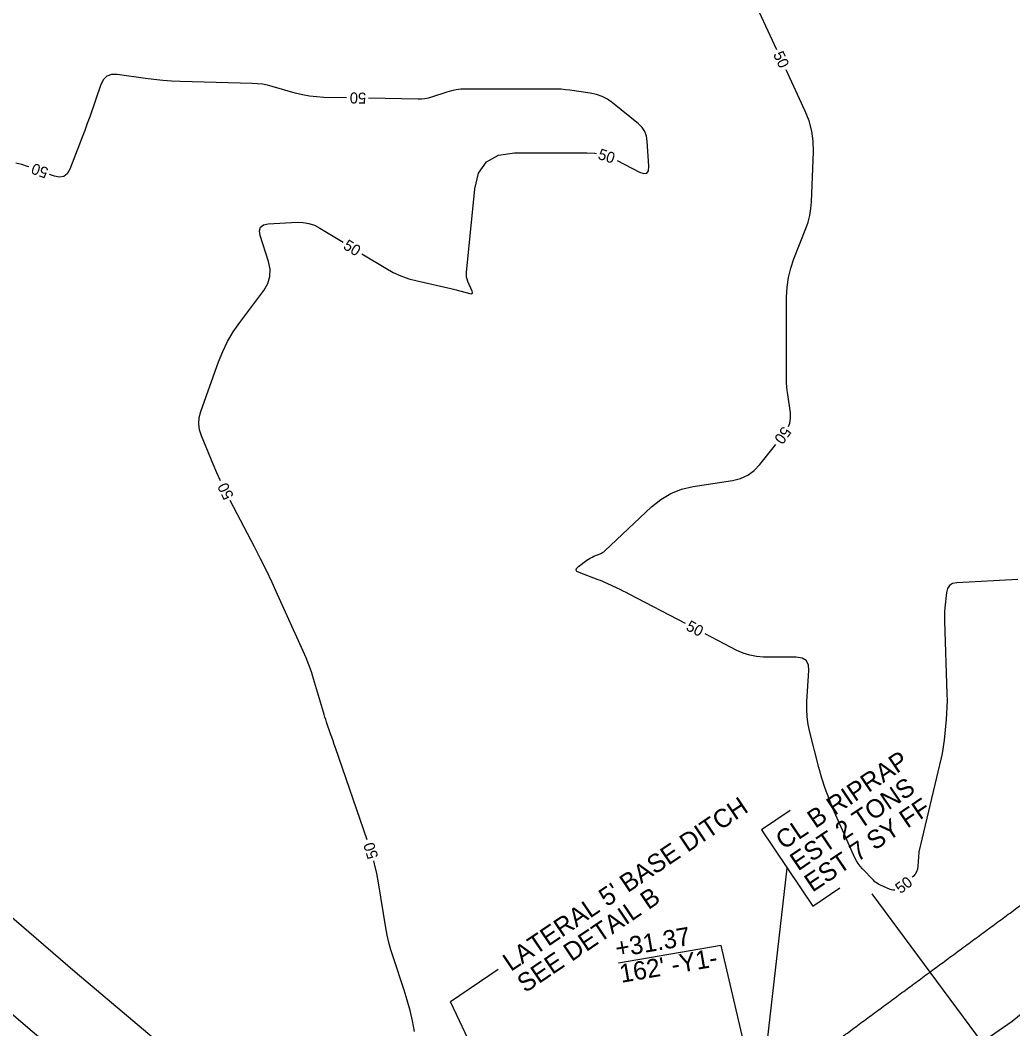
# Model space of a CAD drawing. Extents: x 2384780 to 2405861, y 547869 to 573706.
# Drawn here: x 2392121.2 to 2392391.8, y 553555 to 553830.1 of the extents above; entities that cross this region are included whole.
import ezdxf

# ---------------------------------------------------------------- set-up
doc = ezdxf.new("R2010")
doc.units = 0
for name, color, linetype in [('Breaklines', 7, 'Continuous'), ('Old_Level_5', 7, 'Continuous'), ('Old_Level_61', 7, 'Continuous'), ('Old_Level_63', 7, 'Continuous'), ('Prop Buffer Zone 1', 7, 'Continuous'), ('Prop Buffer Zone 2', 7, 'Continuous'), ('Sheet Plan CELL', 7, 'Continuous')]:
    doc.layers.add(name, color=color, linetype=linetype)

msp = doc.modelspace()

# ---------------------------------------------------------------- linework, layer by layer
at = {"layer": 'Breaklines'}
msp.add_line((2392317.6025, 553488.70725), (2392330.29475, 553598.83), dxfattribs=at)
msp.add_lwpolyline([(2392331.1045, 553614.50125), (2392323.28275, 553609.2255), (2392337.30675, 553588.43425), (2392344.6395, 553593.38025)], dxfattribs=at)
at = {"layer": 'Old_Level_5'}
for p in [(2392251.46575, 553571.12025), (2392281.58, 553471.52125)]:
    msp.add_line(p, (2392238.4535, 553562.3435), dxfattribs=at)
at = {"layer": 'Old_Level_61'}
for points in [[(2392327.47975, 553821.98375), (2392320.29075, 553837.53075), (2392320.1375, 553837.8405), (2392319.96825, 553838.1405), (2392319.783, 553838.43075), (2392319.582, 553838.71175), (2392318.899, 553839.6135), (2392318.74225, 553839.79225), (2392318.5645, 553839.94175), (2392318.36575, 553840.062), (2392318.14625, 553840.15325), (2392286.3615, 553850.74), (2392283.187, 553851.817), (2392280.0255, 553852.92975), (2392276.8765, 553854.07775), (2392273.74, 553855.261), (2392263.51575, 553859.18475), (2392261.307, 553859.8885), (2392259.06275, 553860.31825), (2392256.78325, 553860.47425), (2392254.468, 553860.35625), (2392244.3405, 553859.249), (2392242.21325, 553859.19075), (2392242.176, 553859.19625)], [(2392210.1315, 553808.92625), (2392203.986, 553809.051), (2392202.0025, 553809.155), (2392200.038, 553809.3855), (2392198.09275, 553809.7425), (2392196.16625, 553810.22625), (2392189.9045, 553812.01325), (2392188.55625, 553812.353), (2392187.1945, 553812.60675), (2392185.8195, 553812.7745), (2392184.43125, 553812.85625), (2392164.76075, 553813.40025), (2392162.383, 553813.499), (2392160.011, 553813.66325), (2392157.64425, 553813.8935), (2392155.283, 553814.18925), (2392147.57875, 553815.263), (2392146.06575, 553815.2675), (2392144.82825, 553814.821), (2392143.8665, 553813.9235), (2392143.18025, 553812.575), (2392140.114, 553803.7725), (2392139.448, 553801.8895), (2392138.76425, 553800.01325), (2392138.06275, 553798.1435), (2392137.34325, 553796.28025), (2392134.65925, 553789.42775), (2392133.9705, 553788.20975), (2392133.05475, 553787.4925), (2392131.91175, 553787.27575), (2392130.5415, 553787.55975), (2392129.18825, 553788.047)], [(2392330.66175, 553719.2265), (2392331.01925, 553720.15575), (2392331.236, 553721.55525), (2392331.16025, 553723.0325), (2392330.43625, 553727.9855), (2392330.3005, 553729.04825), (2392330.2035, 553730.114), (2392330.14575, 553731.18225), (2392330.12675, 553732.2535), (2392330.13675, 553754.568), (2392330.262, 553757.252), (2392330.636, 553759.88875), (2392331.25825, 553762.478), (2392332.129, 553765.02), (2392335.37925, 553773.24675), (2392335.99775, 553775.02575), (2392336.45975, 553776.838), (2392336.76525, 553778.68275), (2392336.91475, 553780.5605), (2392337.42625, 553794.16825), (2392337.369, 553797.05075), (2392336.97825, 553799.86625), (2392336.254, 553802.615), (2392335.196, 553805.297), (2392329.998, 553816.538)], [(2392283.95225, 553791.851), (2392290.0665, 553788.656), (2392291.226, 553788.2325), (2392292.0285, 553788.3605), (2392292.474, 553789.04025), (2392292.56275, 553790.2715), (2392292.15625, 553797.0815), (2392291.938, 553798.47325), (2392291.4575, 553799.73025), (2392290.7145, 553800.85225), (2392289.7095, 553801.8395), (2392282.66625, 553807.541), (2392281.2875, 553808.5155), (2392279.81775, 553809.281), (2392278.2565, 553809.83775), (2392276.60425, 553810.18525), (2392271.05775, 553810.979), (2392269.86775, 553811.12775), (2392268.67475, 553811.234), (2392267.47875, 553811.298), (2392266.2795, 553811.31925), (2392242.685, 553811.31925), (2392241.351, 553811.26625), (2392240.0345, 553811.107), (2392238.73475, 553810.842), (2392237.4525, 553810.471), (2392233.2915, 553809.0855), (2392232.394, 553808.828), (2392231.4845, 553808.6495), (2392230.56275, 553808.55025), (2392229.62925, 553808.52975), (2392216.13025, 553808.80425)], [(2392214.35575, 553766.38275), (2392220.82175, 553762.4345), (2392222.85075, 553761.30525), (2392224.951, 553760.3525), (2392227.12275, 553759.576), (2392229.36575, 553758.97575), (2392238.54475, 553756.91275), (2392239.271, 553756.744), (2392239.99475, 553756.565), (2392240.71575, 553756.3755), (2392241.43425, 553756.17575), (2392243.77675, 553755.50625), (2392244.19025, 553755.44075), (2392244.42725, 553755.531), (2392244.48725, 553755.77725), (2392244.3705, 553756.1795), (2392243.22825, 553758.85375), (2392243.02175, 553759.43275), (2392242.89175, 553760.0235), (2392242.838, 553760.626), (2392242.861, 553761.24025), (2392245.11675, 553784.11375), (2392246.15525, 553788.4025), (2392248.3045, 553791.46575), (2392251.564, 553793.30375), (2392255.934, 553793.9165), (2392275.68675, 553793.9165), (2392277.81275, 553793.79175), (2392278.27775, 553793.70725)], [(2392123.54325, 553790.08025), (2392123.1625, 553790.21725), (2392121.56875, 553790.71975), (2392119.9505, 553791.08825)], [(2392175.77725, 553704.41), (2392174.75675, 553706.659), (2392173.75375, 553709.00375), (2392170.56025, 553716.701), (2392170.03675, 553718.3545), (2392169.835, 553720.01575), (2392169.955, 553721.685), (2392170.39675, 553723.362), (2392175.24425, 553736.88325), (2392176.3835, 553739.72675), (2392177.7235, 553742.4625), (2392179.26425, 553745.09025), (2392181.00575, 553747.61025), (2392187.553, 553756.37575), (2392188.65075, 553758.2305), (2392189.237, 553760.1705), (2392189.312, 553762.19575), (2392188.8755, 553764.3065), (2392186.61425, 553771.34025), (2392186.388, 553772.67), (2392186.67775, 553773.645), (2392187.48425, 553774.26475), (2392188.80675, 553774.52975), (2392196.642, 553774.96325), (2392198.2905, 553774.935), (2392199.878, 553774.66425), (2392201.40475, 553774.1515), (2392202.87025, 553773.39625), (2392209.235, 553769.50975)], [(2392302.6005, 553665.50475), (2392287.2475, 553673.53575), (2392286.424, 553673.9605), (2392285.59525, 553674.375), (2392284.762, 553674.78), (2392283.9235, 553675.17475), (2392281.177, 553676.4485), (2392280.58625, 553676.716), (2392279.9905, 553676.97175), (2392279.39, 553677.21625), (2392278.78475, 553677.4495), (2392273.582, 553679.397), (2392272.96325, 553679.72525), (2392272.7175, 553680.1075), (2392272.8455, 553680.54325), (2392273.34675, 553681.03275), (2392275.6675, 553682.775), (2392276.12125, 553683.093), (2392276.593, 553683.37925), (2392277.0825, 553683.6335), (2392277.59, 553683.85575), (2392279.277, 553684.53025), (2392279.62875, 553684.69), (2392279.96075, 553684.8805), (2392280.2735, 553685.10175), (2392280.5665, 553685.3535), (2392293.272, 553697.3355), (2392295.7975, 553699.3925), (2392298.5395, 553701.005), (2392301.4985, 553702.17325), (2392304.67425, 553702.897), (2392315.40225, 553704.535), (2392317.5935, 553705.07075), (2392319.569, 553705.97575), (2392321.32925, 553707.25025), (2392322.87425, 553708.89375), (2392327.17575, 553714.36675)], [(2392215.7645, 553606.50225), (2392207.149, 553631.575), (2392206.815, 553632.547), (2392206.48075, 553633.51925), (2392206.14675, 553634.49125), (2392205.81275, 553635.4635), (2392204.7215, 553638.639), (2392204.49125, 553639.32075), (2392204.26825, 553640.0045), (2392204.0525, 553640.69075), (2392203.84375, 553641.3795), (2392201.153, 553650.42925), (2392200.54425, 553652.3565), (2392199.87125, 553654.25975), (2392199.13375, 553656.13875), (2392198.33175, 553657.994), (2392191.36025, 553673.39825), (2392189.84375, 553676.688), (2392188.282, 553679.956), (2392186.675, 553683.20175), (2392185.02275, 553686.42575), (2392178.44775, 553699.0375)], [(2392393.2035, 553677.523), (2392376.52575, 553676.649), (2392375.38875, 553676.43075), (2392374.54025, 553675.90975), (2392373.98075, 553675.0865), (2392373.71025, 553673.9605), (2392373.2975, 553669.78875), (2392373.224, 553668.89425), (2392373.18, 553667.99875), (2392373.16575, 553667.1025), (2392373.181, 553666.205), (2392373.8495, 553646.2945), (2392373.87925, 553644.55675), (2392373.8515, 553642.82075), (2392373.7665, 553641.0865), (2392373.624, 553639.3545), (2392373.06475, 553633.69875), (2392372.92475, 553632.49025), (2392372.74475, 553631.2885), (2392372.52475, 553630.09325), (2392372.2645, 553628.90475), (2392366.19525, 553603.2335), (2392366.19425, 553603.229), (2392366.1935, 553603.22425), (2392366.193, 553603.2195), (2392366.1925, 553603.2145), (2392366.1915, 553603.199), (2392366.1915, 553603.1955), (2392366.19125, 553603.19225), (2392366.191, 553603.18875), (2392366.19075, 553603.1855), (2392365.957, 553599.2965), (2392365.836, 553598.4975), (2392365.5725, 553597.7665), (2392365.167, 553597.10375), (2392364.61925, 553596.50925), (2392364.396, 553596.307)], [(2392359.6825, 553592.7505), (2392359.135, 553592.751), (2392358.35675, 553592.98625), (2392355.75375, 553594.1375), (2392355.21275, 553594.40825), (2392354.7055, 553594.72725), (2392354.23175, 553595.09425), (2392353.792, 553595.50975), (2392350.801, 553598.617), (2392350.193, 553599.30525), (2392349.6515, 553600.038), (2392349.17625, 553600.8155), (2392348.76725, 553601.6375), (2392342.87625, 553614.87125), (2392341.70425, 553617.662), (2392340.654, 553620.49475), (2392339.72525, 553623.37), (2392338.9185, 553626.28725), (2392336.48175, 553635.88625), (2392336.0405, 553637.95075), (2392335.7615, 553640.03075), (2392335.6445, 553642.126), (2392335.6895, 553644.23675), (2392336.19275, 553652.69725), (2392336.06, 553654.28475), (2392335.44625, 553655.42125), (2392334.35175, 553656.1065), (2392332.776, 553656.341), (2392323.83275, 553656.38475), (2392321.94375, 553656.504), (2392320.10925, 553656.84275), (2392318.32925, 553657.4015), (2392316.60375, 553658.18), (2392307.91725, 553662.72375)], [(2392228.71825, 553554.2515), (2392228.15225, 553557.11275), (2392227.484, 553559.948), (2392226.71375, 553562.75725), (2392225.84125, 553565.54025), (2392222.825, 553574.5895), (2392222.218, 553576.5385), (2392221.68975, 553578.50675), (2392221.2405, 553580.49475), (2392220.87025, 553582.502), (2392218.86025, 553594.7505), (2392218.37525, 553597.36175), (2392217.782, 553599.94525), (2392217.55375, 553600.77725)]]:
    msp.add_lwpolyline(points, dxfattribs=at)
at = {"layer": 'Old_Level_63'}
msp.add_line((2392465.5955, 553440.27425), (2392353.48525, 553591.8015), dxfattribs=at)
msp.add_lwpolyline([(2392322.107, 553535.63125), (2392312.25, 553577.70575), (2392284.3215, 553572.89)], dxfattribs=at)
msp.add_spline([(2392322.107, 553535.63125), (2392325.8135, 553538.37375), (2392329.521, 553541.1165), (2392333.2305, 553543.86075), (2392336.94225, 553546.60625), (2392340.65775, 553549.3545), (2392344.3735, 553552.102), (2392348.0935, 553554.8525), (2392351.814, 553557.6025), (2392355.53775, 553560.35425), (2392359.26675, 553563.109), (2392362.9945, 553565.86175), (2392366.727, 553568.61725), (2392370.46275, 553571.3735), (2392374.19675, 553574.1275), (2392377.936, 553576.8845), (2392381.68125, 553579.644), (2392385.42425, 553582.4005), (2392389.17375, 553585.1605), (2392392.926, 553587.92025), (2392396.6795, 553590.6795), (2392400.43925, 553593.44125), (2392404.19925, 553596.2015), (2392407.96325, 553598.96225), (2392411.72825, 553601.7215), (2392415.49925, 553604.48325), (2392419.27425, 553607.24525), (2392423.0475, 553610.00375), (2392426.82675, 553612.76425), (2392430.6105, 553615.525), (2392434.39825, 553618.286), (2392438.18925, 553621.04675), (2392441.984, 553623.807), (2392445.781, 553626.566), (2392449.57925, 553629.32275), (2392453.38325, 553632.08075), (2392457.19475, 553634.84075), (2392461.00575, 553637.5965), (2392464.82025, 553640.352), (2392468.64175, 553643.10825), (2392472.46475, 553645.8625), (2392476.2925, 553648.61625), (2392480.12425, 553651.36875), (2392483.961, 553654.12075), (2392487.79725, 553656.8685), (2392491.6425, 553659.619), (2392495.49, 553662.366), (2392499.34225, 553665.11275), (2392503.199, 553667.85775), (2392507.05775, 553670.6), (2392510.9275, 553673.34525), (2392514.7955, 553676.08425), (2392518.669, 553678.82275), (2392522.5455, 553681.55825), (2392526.4285, 553684.29325), (2392530.31675, 553687.027), (2392534.2075, 553689.7575), (2392538.10875, 553692.48975), (2392542.00975, 553695.216), (2392545.91125, 553697.93775), (2392549.823, 553700.661), (2392553.73875, 553703.381), (2392557.66125, 553706.10025), (2392561.58625, 553708.81525), (2392565.51625, 553711.52775), (2392569.452, 553714.238), (2392573.39075, 553716.9445), (2392577.34025, 553719.652), (2392581.29, 553722.353), (2392585.24325, 553725.0505), (2392589.20675, 553727.74825), (2392593.1735, 553730.4415), (2392597.14325, 553733.13), (2392601.12125, 553735.8175), (2392605.02475, 553738.44775)], degree=3, dxfattribs=at)
at = {"layer": 'Prop Buffer Zone 1'}
msp.add_lwpolyline([(2392177.634, 553509.85725), (2392164.84625, 553520.049), (2392123.20625, 553555.2065), (2392081.34075, 553591.269), (2392039.88475, 553624.9605), (2391997.7555, 553660.70975), (2391948.74425, 553699.73575), (2391903.893, 553737.29675), (2391883.53775, 553754.1785)], dxfattribs=at)
at = {"layer": 'Prop Buffer Zone 2'}
msp.add_lwpolyline([(2392190.242, 553525.38275), (2392177.53225, 553535.5125), (2392136.1835, 553570.4235), (2392094.17625, 553606.6085), (2392052.6625, 553640.34675), (2392010.45725, 553676.1605), (2391961.39525, 553715.227), (2391916.69675, 553752.66), (2391896.30475, 553769.57225)], dxfattribs=at)
at = {"layer": 'Sheet Plan CELL'}
msp.add_line((2392350.481, 553528.6095), (2392391.61975, 553557.07225), dxfattribs=at)
msp.add_lwpolyline([(2392391.61975, 553557.07225), (2392430.4875, 553588.60425), (2392470.201, 553618.9935), (2392510.01325, 553649.249), (2392553.45175, 553681.27075), (2392592.80775, 553712.2445), (2392635.855, 553744.2385), (2392678.09775, 553771.00725), (2392724.3275, 553791.7585), (2392772.89875, 553822.38), (2392815.1775, 553849.11825), (2392857.30175, 553876.11875), (2392903.20675, 553904.299)], dxfattribs=at)

# ---------------------------------------------------------------- texts
at = {"layer": 'Breaklines'}
for s, p in [('CL B RIPRAP', (2392329.341, 553603.67475)), ('EST 2 TONS ', (2392333.25525, 553597.87125)), ('EST 7 SY FF', (2392337.16975, 553592.068))]:
    msp.add_text(s, height=4.9999995, rotation=33.9995917, dxfattribs=at).set_placement(p)
at = {"layer": 'Old_Level_5'}
for s, p in [("LATERAL 5' BASE DITCH", (2392254.93625, 553570.4455)), ('SEE DETAIL B', (2392258.85075, 553564.642))]:
    msp.add_text(s, height=4.9999995, rotation=33.9999278, dxfattribs=at).set_placement(p)
at = {"layer": 'Old_Level_61'}
for rotation, p in [(294.8163556, (2392326.386, 553820.77525)), (178.8354306, (2392215.523, 553810.317)), (341.8866472, (2392278.478, 553792.317)), (160.19335, (2392129.09625, 553789.6745)), (328.5901639, (2392208.99775, 553767.897)), (234.348825, (2392329.1875, 553719.51875)), (116.4309472, (2392179.4765, 553700.26125)), (332.3865528, (2392302.47075, 553663.88)), (107.3547611, (2392218.847, 553601.8485)), (37.0368028, (2392361.19025, 553591.67325))]:
    msp.add_text('50', height=3, rotation=rotation, dxfattribs=at).set_placement(p)
at = {"layer": 'Old_Level_63'}
for s, p in [('+31.37', (2392283.8575, 553574.391)), ("162' -Y1-", (2392285.047, 553567.49275))]:
    msp.add_text(s, height=5, rotation=9.7834278, dxfattribs=at).set_placement(p)

doc.saveas('drawing.dxf')
